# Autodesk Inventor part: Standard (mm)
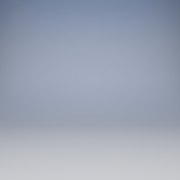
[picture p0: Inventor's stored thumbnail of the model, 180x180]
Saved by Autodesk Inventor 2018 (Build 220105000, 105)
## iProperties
Created: 2017-02
Part Number: Standard (mm)
Material: Ogólny
Document SubType Name: Modeling
Density: 1 g/cm^3
Appearance: Domyślna
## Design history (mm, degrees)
